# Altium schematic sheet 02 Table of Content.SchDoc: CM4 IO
size 297 x 209 mm; Page Create Date: March  8, 1995; Page Number: 2; Page Size: A4; Comment: radxa_1010; Page Count: 19; RevCode: V1.10; Doc: 02 Table of Content; DsnPath: D:\WMS\黄工\[RC126]CM4_IO_V1.10\[RC126]_V1.10\CM4 IO_V1.10.DSN; SchematicName: CM4 IO V1.10; PageName: 02 Table of Content; PageSize: A4; TopSchematic: True
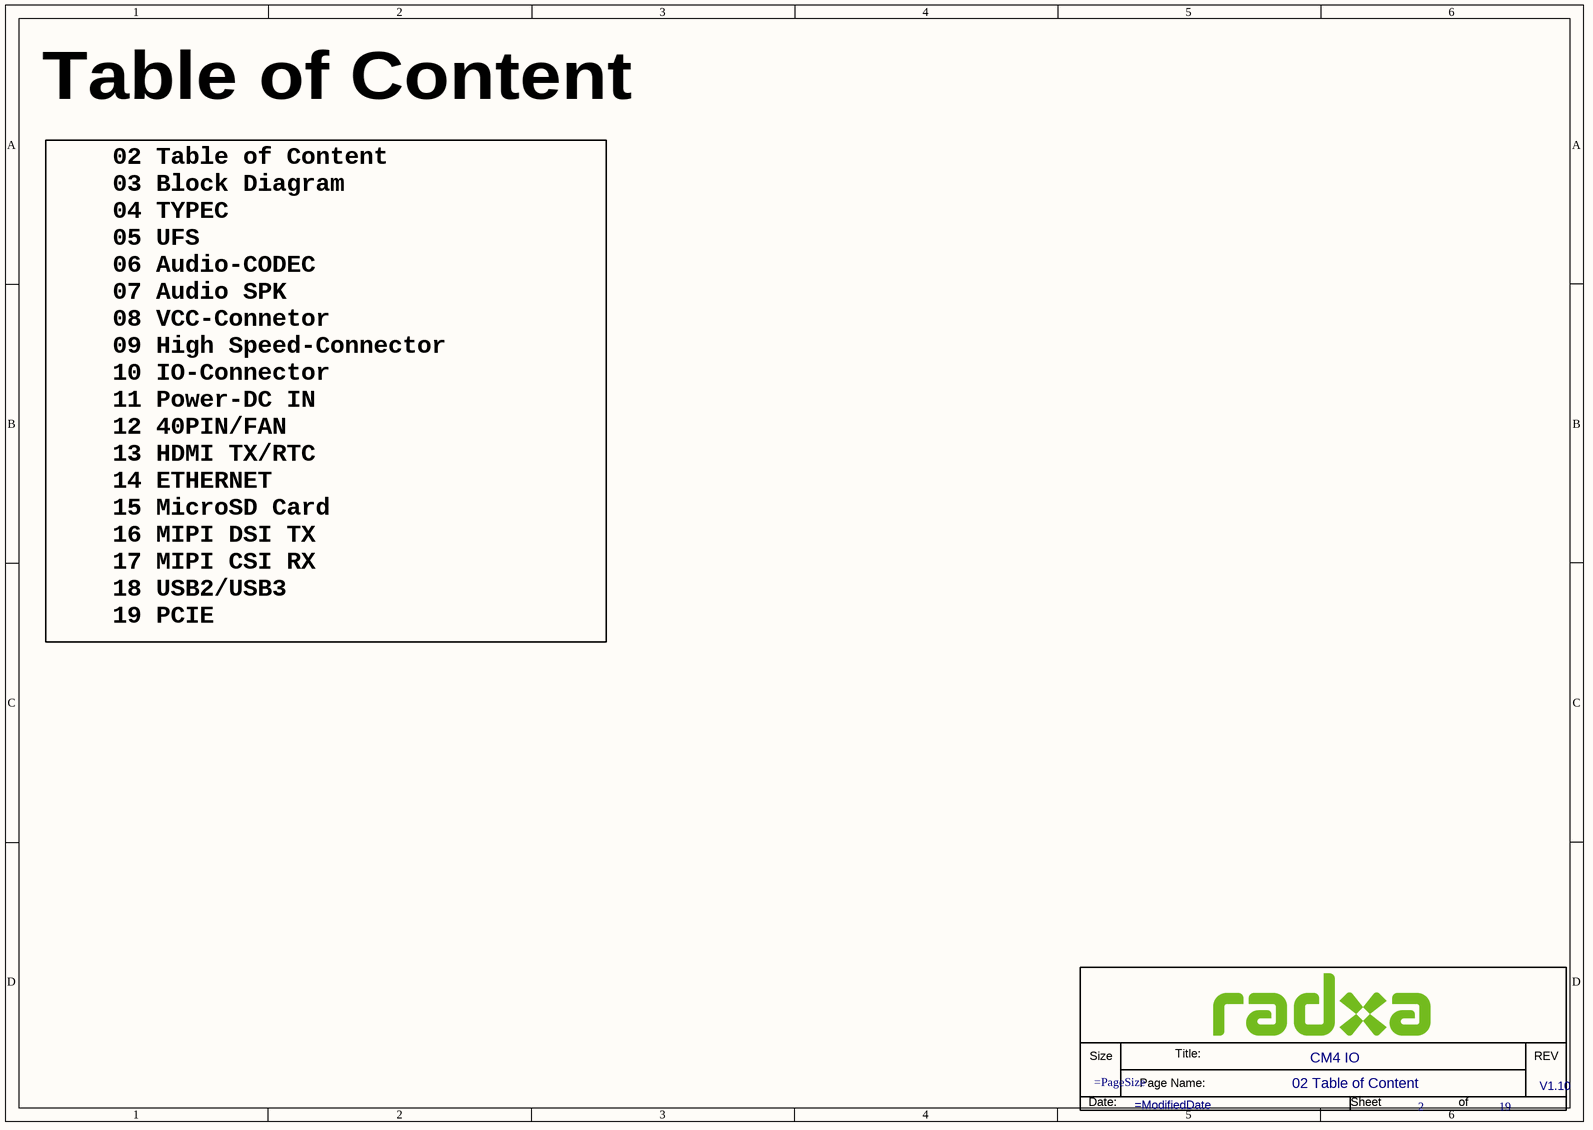
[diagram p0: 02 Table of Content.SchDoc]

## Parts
*  Doc: 02 Table of Content  RevCode: V1.10  Title: CM4 IO  Page Number: 2  Page Count: 19  (hidden comment: radxa_1010)  (graphical)

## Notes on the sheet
- Table of Content
- 02 Table of Content
  03 Block Diagram
  04 TYPEC
  05 UFS
  06 Audio-CODEC
  07 Audio SPK
  08 VCC-Connetor
  09 High Speed-Connector
  10 IO-Connector
  11 Power-DC IN
  12 40PIN/FAN
  13 HDMI TX/RTC
  14 ETHERNET
  15 MicroSD Card
  16 MIPI DSI TX
  17 MIPI CSI RX
  18 USB2/USB3
  19 PCIE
